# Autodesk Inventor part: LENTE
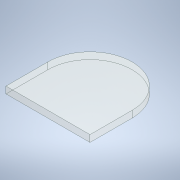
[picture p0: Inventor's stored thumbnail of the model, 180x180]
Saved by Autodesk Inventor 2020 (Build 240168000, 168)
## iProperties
Created: 2022-09
Part Number: LENTE
Material: Vidrio
Document SubType Name: Modeling
Designer: SEBAS
Density: 2.18 g/cm^3
Appearance: Claro
Author: SEBAS
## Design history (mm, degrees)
sketch "Boceto1"
  geometry: L1 (31, 0)-(31, 31); L2 (-31, 31)-(-31, 0); L3 (31, 31)-(-31, 31); A1 r 31 centre (0, 0) between (-31, 0) and (31, 0); 2 further points
  constraints: 6 end point, 3 vertical alignment, 2 point on circle, 1 centre point, 1 coincident, 1 horizontal alignment, 1 midpoint
  dimensions: "d1" = 31 distance of L1.start L1.end; "d2" = 62 distance between parallel lines of L2 L1; "d5" = 31 radius of A1
extrude "Extrusión1" new body sketch "Boceto1" distance "d3" = 5; taper "d4" = 0 deg
node "Sólido1"
